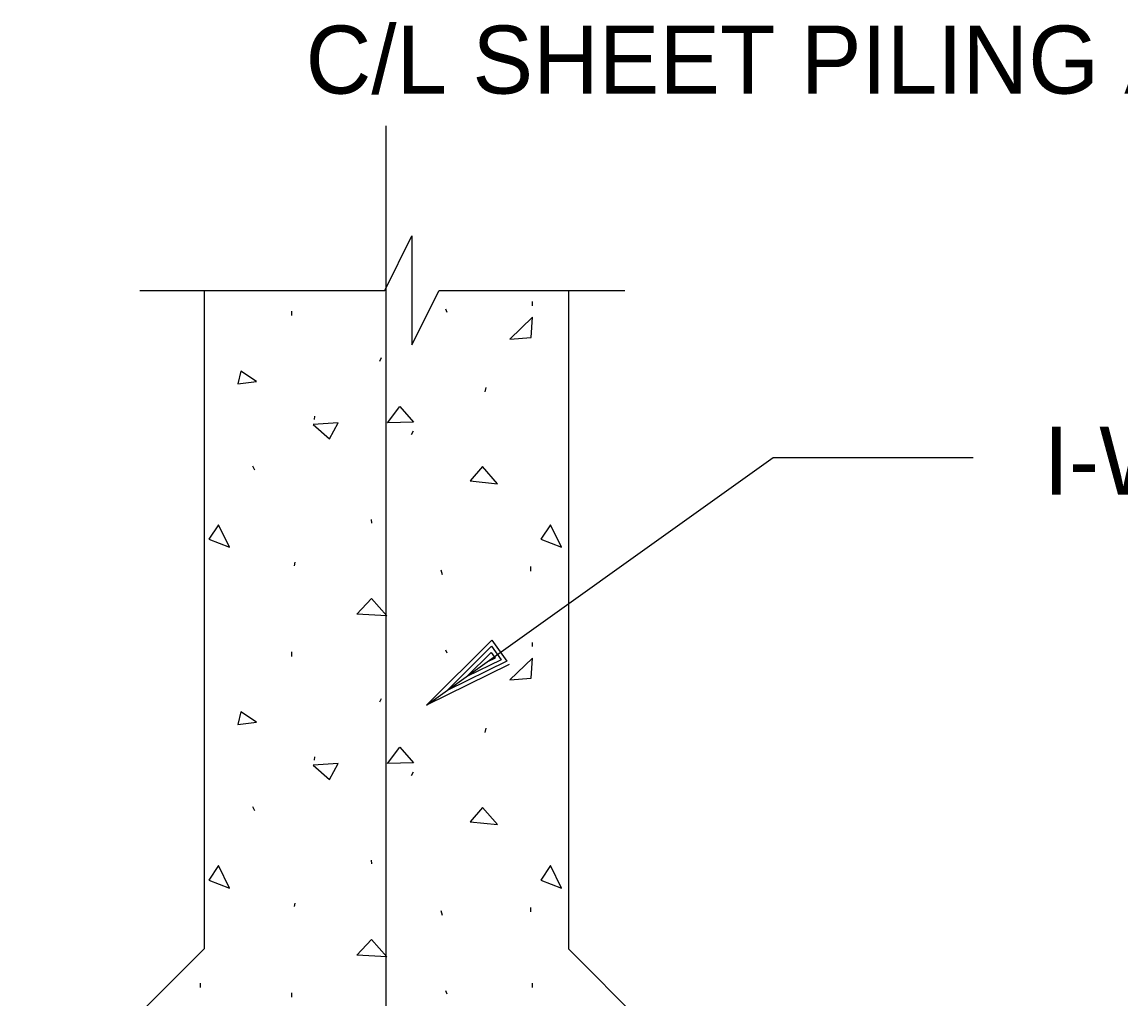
# Model space of a CAD drawing. Extents: x 22411.4 to 22495.4, y 22369.6 to 22415.
# Drawn here: x 22416.291 to 22419.306, y 22396.021 to 22398.699 of the extents above; entities that cross this region are included whole.
import ezdxf

# ---------------------------------------------------------------- set-up
doc = ezdxf.new("R2010")
doc.units = 0
for name, color, linetype in [('Level 1', 7, 'Continuous'), ('Level 2', 7, 'Continuous'), ('Level 4', 7, 'Continuous'), ('Level 7', 7, 'Continuous'), ('Level 8', 7, 'Continuous')]:
    doc.layers.add(name, color=color, linetype=linetype)

msp = doc.modelspace()

# ---------------------------------------------------------------- linework, layer by layer
at = {"layer": 'Level 1'}
for p, q in [((22417.2912, 22389.3264), (22417.2912, 22398.4141)), ((22416.6145, 22397.9624), (22417.2869, 22397.9624)), ((22417.4364, 22397.9624), (22417.9459, 22397.9624))]:
    msp.add_line(p, q, dxfattribs=at)
msp.add_lwpolyline([(22417.2869, 22397.9624), (22417.3614, 22398.1124), (22417.3614, 22397.8127), (22417.4364, 22397.9624)], dxfattribs=at)
at = {"layer": 'Level 2'}
for p, q in [((22417.4019, 22396.8243), (22418.3538, 22397.5037)), ((22418.3538, 22397.5037), (22418.9021, 22397.5037))]:
    msp.add_line(p, q, dxfattribs=at)
msp.add_lwpolyline([(22417.6289, 22396.9355), (22417.4019, 22396.8243), (22417.5809, 22397.0028), (22417.6219, 22396.9453), (22417.4584, 22396.8646), (22417.5799, 22396.9858), (22417.6063, 22396.9489), (22417.5126, 22396.9033), (22417.579, 22396.9687), (22417.5898, 22396.9535), (22417.5691, 22396.9436)], dxfattribs=at)
at = {"layer": 'Level 7'}
for p, q in [((22416.7912, 22397.9625), (22416.7912, 22396.1559)), ((22417.7912, 22397.9625), (22417.7912, 22396.1559)), ((22416.2912, 22395.6559), (22416.7912, 22396.1559)), ((22418.2912, 22395.6559), (22417.7912, 22396.1559))]:
    msp.add_line(p, q, dxfattribs=at)
at = {"layer": 'Level 8'}
for p, q in [((22417.4582, 22397.9018), (22417.4546, 22397.9107)), ((22417.6926, 22397.9201), (22417.6926, 22397.9318)), ((22417.0321, 22397.8932), (22417.0321, 22397.9057)), ((22417.274, 22397.7682), (22417.2786, 22397.778)), ((22417.5632, 22397.6843), (22417.5651, 22397.6964)), ((22417.094, 22397.6082), (22417.0948, 22397.6174)), ((22417.3601, 22397.5666), (22417.3663, 22397.577)), ((22416.9309, 22397.4691), (22416.9253, 22397.4801)), ((22417.2517, 22397.3239), (22417.2509, 22397.3341)), ((22417.0398, 22397.207), (22417.0415, 22397.2164)), ((22417.4457, 22397.1822), (22417.4421, 22397.1947)), ((22417.6882, 22397.1922), (22417.6882, 22397.2047)), ((22417.4582, 22396.9666), (22417.4546, 22396.9755)), ((22417.6926, 22396.9849), (22417.6926, 22396.9966)), ((22417.0321, 22396.958), (22417.0321, 22396.9705)), ((22417.4584, 22396.8646), (22417.4584, 22396.8646)), ((22417.274, 22396.833), (22417.2786, 22396.8428)), ((22417.4019, 22396.8243), (22417.4019, 22396.8243)), ((22417.5632, 22396.7491), (22417.5651, 22396.7612)), ((22417.094, 22396.673), (22417.0948, 22396.6822)), ((22417.3601, 22396.6314), (22417.3663, 22396.6418)), ((22416.9309, 22396.5339), (22416.9253, 22396.5449)), ((22417.2517, 22396.3887), (22417.2509, 22396.3989)), ((22417.0398, 22396.2718), (22417.0415, 22396.2812)), ((22417.4457, 22396.247), (22417.4421, 22396.2595)), ((22417.6882, 22396.257), (22417.6882, 22396.2695)), ((22416.7815, 22396.0497), (22416.7815, 22396.0614)), ((22417.4582, 22396.0314), (22417.4546, 22396.0403)), ((22417.6926, 22396.0497), (22417.6926, 22396.0614)), ((22417.0321, 22396.0228), (22417.0321, 22396.0353))]:
    msp.add_line(p, q, dxfattribs=at)
for points in [[(22417.6894, 22397.8332), (22417.6926, 22397.8889), (22417.6309, 22397.8287)], [(22416.884, 22397.7062), (22416.9346, 22397.7126), (22416.8921, 22397.7412)], [(22417.2946, 22397.5995), (22417.3282, 22397.6439), (22417.3659, 22397.6012)], [(22417.0909, 22397.5947), (22417.1353, 22397.5551), (22417.159, 22397.5995)], [(22417.5963, 22397.4316), (22417.5551, 22397.4791), (22417.5219, 22397.4397)], [(22416.8042, 22397.2797), (22416.8611, 22397.2576), (22416.8311, 22397.3191)], [(22417.7153, 22397.2797), (22417.7721, 22397.2576), (22417.7421, 22397.3191)], [(22417.2109, 22397.0737), (22417.2505, 22397.1166), (22417.293, 22397.0691)], [(22417.6894, 22396.898), (22417.6926, 22396.9537), (22417.6309, 22396.8935)], [(22416.884, 22396.771), (22416.9346, 22396.7774), (22416.8921, 22396.806)], [(22417.2946, 22396.6643), (22417.3282, 22396.7087), (22417.3659, 22396.666)], [(22417.0909, 22396.6595), (22417.1353, 22396.6199), (22417.159, 22396.6643)], [(22417.5963, 22396.4964), (22417.5551, 22396.5439), (22417.5219, 22396.5045)], [(22416.8042, 22396.3445), (22416.8611, 22396.3224), (22416.8311, 22396.3839)], [(22417.7153, 22396.3445), (22417.7721, 22396.3224), (22417.7421, 22396.3839)], [(22417.2109, 22396.1385), (22417.2505, 22396.1814), (22417.293, 22396.1339)]]:
    msp.add_lwpolyline(points, close=True, dxfattribs=at)

# ---------------------------------------------------------------- texts
at = {"layer": 'Level 4'}
for s, height, p in [('C/L SHEET PILING AND I-WALL', 0.186667, (22417.07, 22398.5025)), ('I-WALL', 0.18667, (22419.0959, 22397.4023))]:
    msp.add_text(s, height=height, dxfattribs=at).set_placement(p)

doc.saveas('drawing.dxf')
